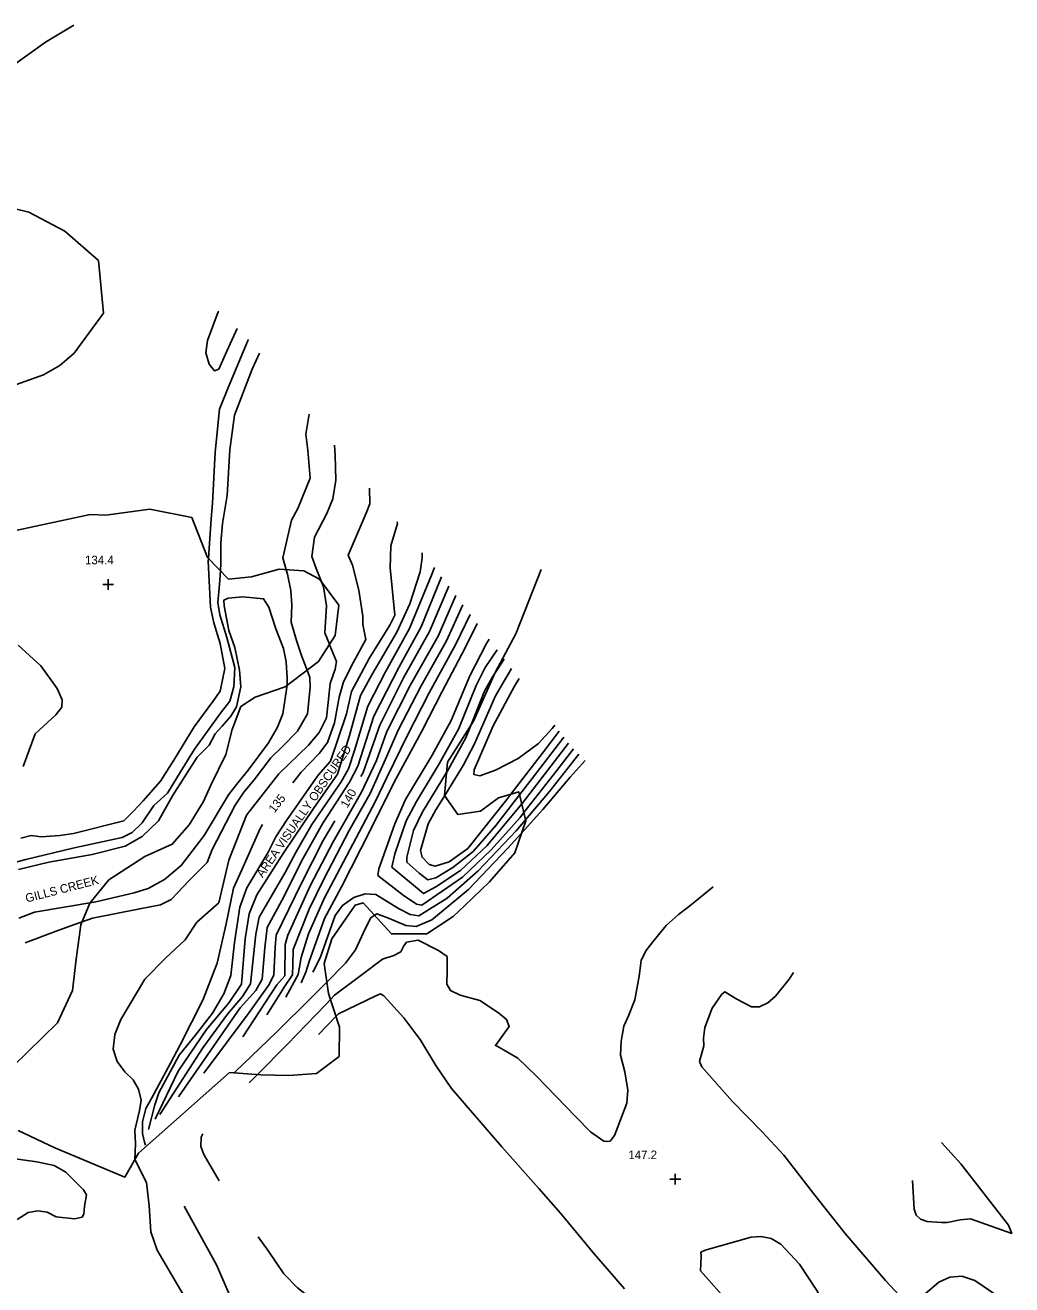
# Model space of a CAD drawing. Extents: x 1467615 to 2003689, y 770235 to 1108726.
# Drawn here: x 2001014.7 to 2001244.8, y 773169.6 to 773463.3 of the extents above; entities that cross this region are included whole.
import ezdxf

# ---------------------------------------------------------------- set-up
doc = ezdxf.new("R2010")
doc.units = 0
for name, color, linetype in [('RD_DTM_Major1', 7, 'Continuous'), ('RD_DTM_Major1_Lbl', 7, 'Continuous'), ('RD_DTM_Major2', 7, 'Continuous'), ('RD_DTM_Minor1', 7, 'Continuous'), ('RD_DTM_Minor2', 7, 'Continuous'), ('RD_DTM_Obscure', 7, 'Continuous'), ('RD_DTM_Spot_Elev', 7, 'Continuous'), ('RD_TX_Misc1', 7, 'Continuous')]:
    doc.layers.add(name, color=color, linetype=linetype)

msp = doc.modelspace()

# ---------------------------------------------------------------- linework, layer by layer
at = {"layer": 'RD_DTM_Major1'}
for points in [[(2001138.22, 773300.11), (2001137.6, 773299.3), (2001134.44, 773295.87), (2001129.73, 773292.36), (2001124.45, 773289.59), (2001120.78, 773288.32), (2001119.4, 773288.59), (2001119.43, 773289.72), (2001123.87, 773299.99), (2001128.89, 773309.23), (2001129.91, 773311)], [(2001143.82, 773293.36), (2001137.02, 773284.62), (2001131.44, 773278.05)], [(2001051.79, 773187.96), (2001059.35, 773174.28), (2001062.59, 773166.73)]]:
    msp.add_lwpolyline(points, dxfattribs=at)
at = {"layer": 'RD_DTM_Major2'}
for points in [[(2001059.87, 773396.69), (2001059.77, 773396.5), (2001057.22, 773389.84), (2001056.89, 773386.93), (2001057.65, 773384.28), (2001058.88, 773382.78), (2001059.86, 773383.13), (2001061.75, 773387.33), (2001064.19, 773392.58)], [(2001095.06, 773355.39), (2001095.11, 773351.76), (2001094.29, 773349.55), (2001090.1, 773339.79), (2001091.09, 773337.41), (2001092.52, 773331.62), (2001093.51, 773325.54), (2001093.5, 773323.57), (2001094.2, 773320.07), (2001091.32, 773314.78), (2001088.98, 773310.21), (2001087.94, 773306.67), (2001086.87, 773300.68), (2001085.27, 773296.09), (2001083.27, 773293.47), (2001079.07, 773289.12), (2001077.14, 773286.63)], [(2001113.5, 773332.52), (2001109.04, 773321.95), (2001102.96, 773311.12), (2001097.45, 773300.12), (2001093.56, 773289.07), (2001093.04, 773288.16)], [(2001070.07, 773276.93), (2001069.52, 773276.01), (2001065.28, 773266.35), (2001063.34, 773262.1), (2001061.59, 773253.79), (2001059.53, 773244.63), (2001056.2, 773235.96), (2001050.88, 773225.55), (2001048.65, 773221.28), (2001044.29, 773213.24), (2001042.88, 773210.73), (2001042.08, 773207.64), (2001042.11, 773204.92), (2001042.58, 773202.85), (2001042.8, 773202.19)], [(2001086.98, 773277.81), (2001084.23, 773273.25), (2001079.14, 773263.24), (2001073.28, 773251.14), (2001073.05, 773248.33), (2001072.7, 773241.92), (2001071.64, 773239.62), (2001066.95, 773233.07), (2001056.43, 773218.99)], [(2001131.44, 773278.05), (2001129.26, 773275.48), (2001120.38, 773266.14), (2001113.17, 773259.78), (2001106.56, 773255.63), (2001104.52, 773255.93), (2001101.78, 773257.35), (2001096.52, 773260.59), (2001094.05, 773260.76), (2001091.39, 773259.93), (2001088.72, 773258.07), (2001087.04, 773255.71), (2001083.57, 773245.88), (2001081.85, 773242.55)]]:
    msp.add_lwpolyline(points, dxfattribs=at)
at = {"layer": 'RD_DTM_Minor1'}
for p, q in [((2001124.18, 773312.07), (2001126.45, 773315.54)), ((2001068.83, 773218.6), (2001066.97, 773216.73))]:
    msp.add_line(p, q, dxfattribs=at)
for points in [[(2001013.69, 773273.76), (2001016.17, 773274.38), (2001018.49, 773274.07), (2001022.83, 773274.38), (2001026, 773274.83), (2001037.75, 773277.84), (2001040, 773280.04), (2001042.23, 773282.49), (2001046.31, 773287.05), (2001049.38, 773291.98), (2001054.18, 773299.72), (2001058.47, 773305.61), (2001060.23, 773308.06), (2001061.32, 773313.36), (2001060.24, 773319.14), (2001058.74, 773323.99), (2001057.97, 773327.64), (2001057.42, 773338.37), (2001057.46, 773339)], [(2001003.94, 773265.92), (2001014.9, 773268.8), (2001025.88, 773271.43), (2001037.34, 773273.95), (2001039.71, 773275.06), (2001041.99, 773277.31), (2001044.72, 773281.36), (2001047.9, 773284.28), (2001050.97, 773289.24), (2001054.23, 773294.53), (2001060.29, 773302.91), (2001062.44, 773305.71), (2001063.42, 773309.02), (2001063.6, 773313.54), (2001061.76, 773320.52), (2001060.1, 773325.86), (2001059.67, 773328.74), (2001060.09, 773332.94), (2001060.27, 773336.09)], [(2001075.64, 773336.37), (2001075.95, 773335.31), (2001076.72, 773331.54), (2001076.96, 773328.09), (2001076.73, 773324.16), (2001077.99, 773319.84), (2001079.29, 773316.1), (2001080.5, 773312.94)], [(2001083.83, 773333.54), (2001084.3, 773332.4), (2001085, 773327.92), (2001084.64, 773321.63), (2001085.72, 773318.97)], [(2001013.14, 773266.49), (2001020.27, 773268.13), (2001030.39, 773269.99), (2001038.02, 773271.91), (2001042.02, 773274.12), (2001045.8, 773277.83), (2001049.08, 773283.61), (2001054.85, 773292.66), (2001057.63, 773295.44), (2001059.06, 773298.08), (2001060.7, 773299.87), (2001062.7, 773302.22), (2001064.05, 773304.36), (2001065.05, 773309.06), (2001064.69, 773312.91), (2001063.62, 773318.26), (2001062.2, 773322.19), (2001061.13, 773327.96), (2001061.06, 773329.24), (2001062.06, 773329.71), (2001065.46, 773330.01), (2001070.35, 773329.58), (2001071.54, 773327.6), (2001073.18, 773322.61), (2001074.96, 773317.98), (2001075.6, 773314.91), (2001075.82, 773311.06), (2001075.82, 773309.42)], [(2001013.1, 773318.77), (2001018.38, 773313.94), (2001022.22, 773308.63), (2001023.39, 773306.01), (2001023.31, 773304.3), (2001021.9, 773302.53), (2001017.04, 773298.06), (2001014.25, 773290.44)], [(2001112.58, 773283.68), (2001116.89, 773290.7), (2001119.5, 773295.79), (2001124.39, 773306.98), (2001128.12, 773313.35)], [(2001113.04, 773289.14), (2001117.53, 773297.19), (2001118.67, 773300.05)], [(2001139.29, 773298.7), (2001135.63, 773293.93), (2001128.03, 773284)], [(2001140.36, 773297.29), (2001140.14, 773296.99), (2001132.95, 773287.68), (2001130.03, 773283.89)], [(2001141.43, 773295.89), (2001139.89, 773293.87), (2001130.62, 773281.88), (2001130.54, 773281.78)], [(2001142.59, 773294.57), (2001138.7, 773289.54), (2001131.03, 773279.75)], [(2001145.32, 773291.9), (2001141.8, 773287.95), (2001135.47, 773280.48), (2001130.5, 773274.95)], [(2001175.18, 773262.44), (2001169.72, 773257.97), (2001167.13, 773255.96), (2001164.25, 773253.37), (2001161.08, 773249.62), (2001159.5, 773247.46), (2001158.42, 773245.2), (2001157.91, 773241.56), (2001156.91, 773236.09), (2001155.47, 773232.35), (2001154.32, 773229.9), (2001153.74, 773226.45), (2001153.6, 773223.14), (2001154.6, 773219.25), (2001155.29, 773215.02), (2001155.06, 773211.94), (2001152.99, 773206.43), (2001152.16, 773204.43), (2001151.15, 773203.13), (2001150.43, 773202.99), (2001149.71, 773203.13), (2001146.54, 773205.29), (2001143.15, 773208.8), (2001133.94, 773218.34), (2001129.64, 773222.47), (2001124.84, 773225.25), (2001124.4, 773225.38), (2001127.6, 773229.81), (2001126.96, 773231.49), (2001125.1, 773233.03), (2001120.74, 773235.92), (2001116.2, 773237.16), (2001113.92, 773238.22), (2001113.1, 773239.7), (2001113.18, 773242.89), (2001113.12, 773246.16), (2001111.12, 773247.54), (2001106.4, 773249.96), (2001103.69, 773249.52), (2001103.04, 773248.64), (2001102.34, 773247.26), (2001100.7, 773246.38), (2001098.04, 773245.54), (2001093.63, 773242.17), (2001086.91, 773237.13), (2001085.91, 773236.11)], [(2001031.25, 773258.88), (2001016.92, 773256.51), (2001013.23, 773255.09)], [(2001096.2, 773255.78), (2001095.34, 773255.19), (2001094.12, 773252.75), (2001091.78, 773247.69), (2001089.46, 773244.65), (2001085.06, 773240.17)], [(2001028.03, 773254.29), (2001025.98, 773253.57), (2001021.96, 773252.11), (2001014.7, 773249.39)], [(2001193.92, 773242.44), (2001192.88, 773240.87), (2001189.73, 773236.94), (2001187.92, 773235.33), (2001186.02, 773234.42), (2001184.1, 773234.46), (2001180.7, 773236.2), (2001177.92, 773237.95), (2001177.23, 773237.38), (2001174.93, 773234.08), (2001173.22, 773229.61), (2001172.91, 773227.09), (2001172.98, 773225.35), (2001172, 773221.65), (2001172.56, 773220.4), (2001179.63, 773212.44), (2001186.64, 773205.27), (2001191.7, 773199.84), (2001198.57, 773190.9), (2001205.95, 773181.54), (2001215.34, 773170.61), (2001219.65, 773166.02)], [(2001154.47, 773168.66), (2001147.42, 773176.84), (2001139.55, 773186.34), (2001134.53, 773192.05), (2001125.89, 773201.77), (2001114.15, 773215.37), (2001110.47, 773220.71), (2001106.89, 773226.79), (2001105.83, 773228.16), (2001103.02, 773231.9), (2001098.39, 773237.01), (2001097.57, 773237.45), (2001096.53, 773237.01), (2001087.81, 773232.8), (2001087.21, 773232.19)], [(2001056.14, 773204.79), (2001055.74, 773204.05), (2001055.73, 773201.88), (2001056.38, 773199.98), (2001059.96, 773193.89)], [(2001228.46, 773202.81), (2001232.96, 773197.83), (2001244.06, 773183.51), (2001244.83, 773181.58), (2001235.17, 773185), (2001232.8, 773184.72), (2001229.73, 773184.15), (2001228.44, 773184.11), (2001225.09, 773184.4), (2001223.55, 773184.93), (2001222.49, 773185.84), (2001222.08, 773187.25), (2001221.67, 773193.95)], [(2001011.33, 773199.17), (2001017.49, 773198.26), (2001021.5, 773197.46), (2001024.23, 773195.84), (2001028.32, 773191.78), (2001029, 773190.56), (2001028.56, 773187.94), (2001028.42, 773186.05), (2001028.01, 773185.37), (2001026.25, 773184.97), (2001021.97, 773185.44), (2001019.9, 773186.53), (2001017.72, 773186.83), (2001015.47, 773186.48), (2001012.89, 773184.8)], [(2001040.3, 773198.8), (2001043.05, 773193.47), (2001043.63, 773188.06), (2001044.06, 773181.93), (2001045.49, 773177.71), (2001051.58, 773167.37)], [(2001069.04, 773180.79), (2001071.45, 773177.44), (2001075.07, 773172.18), (2001078.27, 773168.92), (2001084.33, 773164.12), (2001085.17, 773162.73)], [(2001184.93, 773158.27), (2001179.02, 773165.25), (2001172.23, 773172.88), (2001172.38, 773176.31), (2001172.34, 773177.18), (2001173.3, 773177.67), (2001184.05, 773180.71), (2001186.37, 773180.91), (2001188.68, 773180.44), (2001190.96, 773179.1), (2001195.34, 773174.39), (2001199.39, 773168.25), (2001202.6, 773162.28), (2001204.06, 773158.02), (2001203.97, 773156.68), (2001203.34, 773155.68), (2001200.53, 773154.15), (2001196.45, 773153.06), (2001192.54, 773152.8), (2001189.62, 773153.42), (2001187.77, 773154.59), (2001184.93, 773158.27)], [(2001221.44, 773164.78), (2001227.81, 773170.23), (2001230.34, 773171.35), (2001233.19, 773171.59), (2001236.23, 773170.63), (2001241.79, 773166.83)]]:
    msp.add_lwpolyline(points, dxfattribs=at)
at = {"layer": 'RD_DTM_Minor2'}
msp.add_line((2001087.21, 773232.19), (2001083.11, 773228.01), dxfattribs=at)
for points in [[(2001057.46, 773339), (2001058.1, 773348.21), (2001058.39, 773351.88), (2001059.05, 773363.76), (2001060.08, 773373.8), (2001062.13, 773379.04), (2001066.55, 773389.6), (2001066.79, 773390.05)], [(2001060.27, 773336.09), (2001060.36, 773337.88), (2001060.37, 773342.66), (2001060.76, 773347.16), (2001061.88, 773353.66), (2001062.46, 773364.36), (2001063.52, 773372.44), (2001067.66, 773383.17), (2001069.36, 773386.89)], [(2001080.98, 773372.65), (2001080.17, 773367.99), (2001080.63, 773364.25), (2001081.23, 773357.69), (2001078.34, 773350.67), (2001076.88, 773347.95), (2001074.82, 773339.12), (2001075.64, 773336.37)], [(2001086.87, 773365.43), (2001087.05, 773363.1), (2001087.15, 773357.26), (2001086.52, 773352.92), (2001085.09, 773349.48), (2001082.23, 773343.99), (2001081.55, 773339.47), (2001082.56, 773336.66), (2001083.83, 773333.54)], [(2001101.5, 773347.5), (2001101.56, 773347.18), (2001100, 773341.92), (2001099.83, 773336.79), (2001100.92, 773325.75), (2001099.79, 773323.47), (2001094.94, 773315.66), (2001090.84, 773307.99), (2001089.66, 773302.79), (2001085.95, 773291.73), (2001083.09, 773288.46), (2001075.7, 773277.88), (2001073.18, 773274.04), (2001071.36, 773270.31), (2001066.43, 773262.2), (2001064.81, 773257.69), (2001063.55, 773249.42), (2001062.72, 773241.74), (2001061.06, 773237.43), (2001058.46, 773232.99), (2001054.37, 773227.71), (2001050.64, 773223.16), (2001045.93, 773214.36), (2001044.95, 773211.6), (2001043.53, 773205.83)], [(2001107.35, 773340.33), (2001107.3, 773339.15), (2001106.88, 773335.9), (2001104.42, 773328.44), (2001101.38, 773321.78), (2001095.56, 773311.88), (2001092.97, 773307.03), (2001090.36, 773297.68), (2001087.59, 773288.7), (2001081.94, 773280.69), (2001075.03, 773270.39), (2001068.79, 773260.53), (2001066.95, 773256.12), (2001066.03, 773250.31), (2001065.15, 773239.74), (2001062.3, 773235.41), (2001057.06, 773229.14), (2001050.39, 773219.4), (2001045.03, 773208.2)], [(2001110.17, 773336.88), (2001109.49, 773335.13), (2001104.4, 773322.67), (2001098.76, 773312.57), (2001094.65, 773304.57), (2001091.52, 773294.17), (2001090.17, 773289.96), (2001088.39, 773286.87), (2001081.59, 773276.93), (2001077.91, 773270.6), (2001075.33, 773265.72), (2001069.3, 773255.34), (2001068.52, 773251.41), (2001067.27, 773239.78), (2001065.41, 773236.81), (2001061.94, 773232.72), (2001056.15, 773224.87), (2001046.17, 773209.36)], [(2001111.82, 773334.71), (2001107.05, 773323.02), (2001101.92, 773313.74), (2001096.04, 773302.21), (2001092.33, 773290.58), (2001090.41, 773286.84), (2001084.13, 773277.25), (2001079.49, 773268.93), (2001074.62, 773259.26), (2001071.2, 773252.93), (2001070.65, 773248.15), (2001069.99, 773240.85), (2001068.53, 773238.21), (2001064.91, 773234.2), (2001050.47, 773213.46)], [(2001115.17, 773330.32), (2001111.02, 773320.88), (2001104.6, 773309.54), (2001099.1, 773298.67), (2001096.65, 773291.84), (2001093.2, 773284.49), (2001086.53, 773272.94), (2001081.26, 773262.8), (2001075.98, 773251.14), (2001075.39, 773248.99), (2001075.3, 773241.69), (2001073.41, 773239.57), (2001065.51, 773227.4)], [(2001116.82, 773328.16), (2001113, 773319.8), (2001107.05, 773309.32), (2001101.69, 773298.91), (2001099.04, 773292.89), (2001095.23, 773284.19), (2001090.32, 773275.54), (2001084.4, 773264.18), (2001080.93, 773257.17), (2001077.23, 773247.81), (2001077.18, 773244.23), (2001077.08, 773241.89), (2001075.29, 773239.26), (2001071.1, 773232.58)], [(2001118.52, 773325.93), (2001115.16, 773319.01), (2001108.97, 773307.68), (2001103.79, 773297.63), (2001099.18, 773288.06), (2001096.42, 773282.36), (2001091.12, 773272.33), (2001084.51, 773259.87), (2001080.79, 773251.45), (2001079.07, 773245.94), (2001078.43, 773241.98), (2001075.51, 773236.68)], [(2001120.12, 773323.83), (2001117.35, 773318.18), (2001111.96, 773307.96), (2001107.21, 773298.74), (2001100.81, 773286.79), (2001095.27, 773275.74), (2001088.48, 773262.44), (2001084.51, 773255), (2001080.95, 773245.02), (2001080.19, 773242.5), (2001079.11, 773240.01)], [(2001085.72, 773318.97), (2001085.82, 773318.71), (2001087.31, 773314.94), (2001087.02, 773313.2), (2001085.83, 773309.8), (2001085.42, 773305.4), (2001085, 773301.8), (2001083.26, 773298.42), (2001080.82, 773295.45), (2001073.93, 773288.74), (2001066.33, 773279.11), (2001062.24, 773268.6), (2001059.88, 773258.7), (2001054.74, 773254.15), (2001052.03, 773250.06), (2001047.54, 773245.84), (2001042.62, 773240.92), (2001037.02, 773231.48), (2001035.66, 773227.96), (2001035.27, 773224.59), (2001036.19, 773221.7), (2001038, 773219.29), (2001039.9, 773217.42), (2001041.13, 773215.2), (2001041.75, 773212.69), (2001041.39, 773210.26), (2001040.3, 773205.68), (2001040.44, 773202.48), (2001040.3, 773198.8)], [(2001131.03, 773279.75), (2001130.14, 773278.6), (2001123.41, 773271.07), (2001116.74, 773264.68), (2001107.28, 773258.14), (2001105.96, 773258.38), (2001102.86, 773260.49), (2001096.98, 773265.07), (2001097.18, 773266.63), (2001100.97, 773277.12), (2001103.42, 773282.78), (2001109.63, 773293.13), (2001114.06, 773301.22), (2001118.4, 773311.61), (2001122.33, 773319.15), (2001122.93, 773320.16)], [(2001130.54, 773281.78), (2001122.48, 773272.04), (2001116.24, 773266.23), (2001110.54, 773262.38), (2001107.64, 773260.85), (2001100.24, 773267.01), (2001100.94, 773270.1), (2001103.59, 773277.77), (2001106.03, 773282.33), (2001111.31, 773291.09), (2001115.8, 773299.21), (2001119.92, 773309.38), (2001122.05, 773313.6), (2001124.78, 773317.72)], [(2001080.5, 773312.94), (2001080.73, 773312.34), (2001081.1, 773311.21), (2001081.19, 773308.9), (2001080.6, 773302.76), (2001078.26, 773298.68), (2001074.66, 773295.07), (2001072.05, 773292.5), (2001068.17, 773287.36), (2001065.75, 773284.51), (2001063.67, 773281.44), (2001058.31, 773271.11), (2001057.14, 773268.08), (2001052.91, 773263.81), (2001050.43, 773261.14), (2001048.75, 773259.47), (2001046.27, 773258.21), (2001041.45, 773257.32), (2001030.4, 773255.13), (2001028.03, 773254.29)], [(2001118.67, 773300.05), (2001121.87, 773308.08), (2001123.64, 773311.25), (2001124.18, 773312.07)], [(2001075.82, 773309.42), (2001074.82, 773302.72), (2001073.58, 773299.67), (2001071.45, 773295.98), (2001066.73, 773289.64), (2001064.33, 773286.65), (2001062.15, 773283.85), (2001056.49, 773274.42), (2001051.1, 773267.42), (2001047.25, 773264.11), (2001043.41, 773262.01), (2001040.17, 773261.05), (2001031.25, 773258.88)], [(2001130.03, 773283.89), (2001124.49, 773276.7), (2001119.21, 773270.68), (2001114.5, 773266.93), (2001110.47, 773264.53), (2001108.62, 773264.06), (2001106.6, 773265.61), (2001103.76, 773268.18), (2001103.72, 773269.33), (2001105.26, 773275.56), (2001107.34, 773279.75), (2001112.99, 773289.05), (2001113.04, 773289.14)], [(2001128.03, 773284), (2001127.08, 773282.75), (2001118, 773271.38), (2001113.59, 773268.21), (2001110.35, 773267.24), (2001108.97, 773267.63), (2001107.29, 773269.32), (2001106.9, 773270.88), (2001108.75, 773277.14), (2001110.53, 773280.35), (2001112.58, 773283.68)], [(2001130.5, 773274.95), (2001127.24, 773271.33), (2001118.14, 773261.82), (2001109.6, 773254.74), (2001105.92, 773253.14), (2001103.48, 773253.38), (2001099.49, 773255.09), (2001096.75, 773256.15), (2001096.2, 773255.78)], [(2001085.06, 773240.17), (2001081.62, 773236.66), (2001073.25, 773228.44), (2001063.79, 773219.37), (2001063.46, 773219.01)], [(2001085.91, 773236.11), (2001084.83, 773235.01), (2001075.83, 773225.63), (2001068.83, 773218.6)]]:
    msp.add_lwpolyline(points, dxfattribs=at)
at = {"layer": 'RD_DTM_Obscure'}
for points in [[(2001026.1, 773463.35), (2001019.51, 773459.41), (2001011.77, 773453.84)], [(2001009.2, 773421.31), (2001015.62, 773419.75), (2001023.98, 773415.31), (2001031.86, 773408.47), (2001032.98, 773396.18), (2001026.13, 773386.83), (2001022.79, 773383.96), (2001019.01, 773381.81), (2001011.39, 773379.06)], [(2001012.17, 773345.42), (2001029.93, 773349.25), (2001033.53, 773349.08), (2001043.78, 773350.45), (2001053.59, 773348.54), (2001057.28, 773339.19), (2001062.16, 773334.13), (2001067.48, 773334.71), (2001073.95, 773336.46), (2001079.69, 773336.13), (2001083.35, 773334.19), (2001087.86, 773328.09), (2001087.04, 773321.03), (2001083.17, 773314.98), (2001075.4, 773309.03), (2001068.39, 773306.64), (2001065.01, 773304.45), (2001063.04, 773299.14), (2001061.53, 773293.3), (2001058.06, 773286.14), (2001056.31, 773282.28), (2001052.97, 773276.87), (2001049.03, 773272.39), (2001042.66, 773269.46), (2001034.26, 773264.05), (2001029.85, 773258.63), (2001027.71, 773253.52), (2001026.62, 773245.51), (2001025.78, 773238.26), (2001022.28, 773230.73), (2001011.96, 773220.58)], [(2001013.07, 773205.57), (2001021.64, 773201.51), (2001038, 773194.72), (2001041.15, 773200.32), (2001062.36, 773219.09), (2001069.68, 773218.54), (2001076.26, 773218.43), (2001082.69, 773218.91), (2001087.93, 773222.88), (2001088.05, 773229.65), (2001085.45, 773237.51), (2001084.43, 773244.56), (2001086.22, 773250.25), (2001091.66, 773258.17), (2001093.54, 773258.71), (2001100.16, 773251.43), (2001108.4, 773251.48), (2001114.51, 773255.48), (2001117.21, 773257.98), (2001123.06, 773263.55), (2001128.9, 773270.37), (2001131.5, 773277.83), (2001129.87, 773284.54), (2001125.12, 773283.15), (2001120.91, 773280.08), (2001115.62, 773279.31), (2001112.56, 773283.71), (2001113.24, 773291.51), (2001119.29, 773301.04), (2001124.32, 773312.38), (2001129.17, 773321.42), (2001135.05, 773336.39)]]:
    msp.add_lwpolyline(points, dxfattribs=at)
at = {"layer": 'RD_DTM_Spot_Elev'}
for p, q in [((2001032.85, 773332.94), (2001035.35, 773332.94)), ((2001034.1, 773331.69), (2001034.1, 773334.19)), ((2001165.11, 773194.23), (2001167.61, 773194.23)), ((2001166.36, 773192.98), (2001166.36, 773195.48))]:
    msp.add_line(p, q, dxfattribs=at)

# ---------------------------------------------------------------- texts
at = {"layer": 'RD_DTM_Major1_Lbl'}
for s, rotation, p in [('140', 60.1682, (2001089.88, 773280.64)), ('135', 52.2082, (2001072.88, 773279.51))]:
    msp.add_text(s, height=2, rotation=rotation, dxfattribs=at).set_placement(p)
at = {"layer": 'RD_DTM_Spot_Elev'}
for s, p in [('134.4', (2001028.69, 773337.63)), ('147.2', (2001155.4, 773198.91))]:
    msp.add_text(s, height=2, dxfattribs=at).set_placement(p)
at = {"layer": 'RD_TX_Misc1'}
for s, rotation, p in [('AREA VISUALLY OBSCURED', 55.4258, (2001070.12, 773264.4)), ('GILLS CREEK', 14.6098, (2001015.07, 773258.72))]:
    msp.add_text(s, height=2, rotation=rotation, dxfattribs=at).set_placement(p)

doc.saveas('drawing.dxf')
